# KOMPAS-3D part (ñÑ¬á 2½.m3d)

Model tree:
1. Эскиз:1
2. Операция выдавливания:1
     Расстояние 1 = 0.6
3. Эскиз:2
4. Вырезать элемент выдавливания:1
     Толщина стенки 1 = 3; Толщина стенки 2 = 3; Расстояние 1 = 10
5. Эскиз:3
6. Вырезать элемент выдавливания:2
     Толщина стенки 1 = 3; Толщина стенки 2 = 3; Расстояние 1 = 10
7. Эскиз:4
8. Вырезать элемент выдавливания:3
     Толщина стенки 1 = 3; Толщина стенки 2 = 3; Расстояние 1 = 10
9. Эскиз:5
10. Вырезать элемент выдавливания:4
     Толщина стенки 1 = 3; Толщина стенки 2 = 3; Расстояние 1 = 10
11. Эскиз:6
12. Вырезать элемент выдавливания:5
     Расстояние 1 = 10
